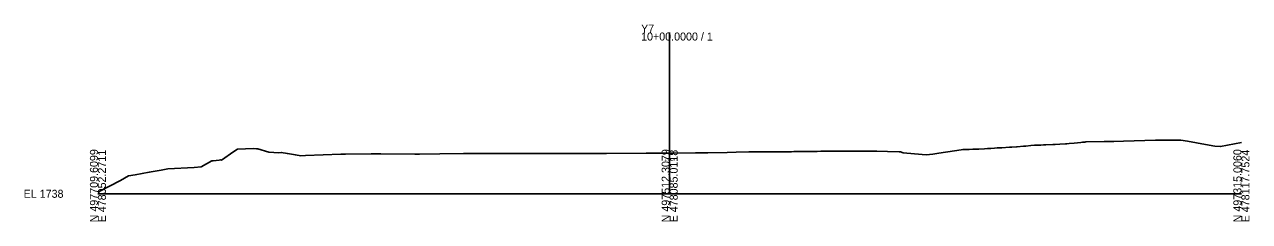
# Model space of a CAD drawing. Extents: x -26 to 403, y -10 to 4071.
# Drawn here: x -25.7 to 402.8, y -9.7 to 59.2 of the extents above; entities that cross this region are included whole.
import ezdxf

# ---------------------------------------------------------------- set-up
doc = ezdxf.new("R2010")
doc.units = 0
for name, color, linetype in [('Exist Cross Section Cell', 7, 'Continuous'), ('Exist XS Center Line Elevation Label', 7, 'Continuous'), ('Exist XS Ground Line', 7, 'Continuous'), ('Scratch_Level_5', 7, 'Continuous')]:
    doc.layers.add(name, color=color, linetype=linetype)

msp = doc.modelspace()

# ---------------------------------------------------------------- linework, layer by layer
at = {"layer": 'Exist Cross Section Cell'}
for p, q in [((200, 0), (200, 56.4)), ((0, 0), (200, 0)), ((200, 0), (400, 0))]:
    msp.add_line(p, q, dxfattribs=at)
at = {"layer": 'Exist XS Ground Line'}
msp.add_lwpolyline([(0, 0.58), (7.9, 4.61), (10.65, 6.28), (13.04, 6.64), (17.96, 7.51), (22.12, 8.29), (24.49, 8.76), (33.66, 9.18), (36.14, 9.4), (39.88, 11.54), (40.31, 11.56), (42.43, 11.79), (42.91, 11.84), (43.25, 11.77), (47.51, 14.77), (48.78, 15.56), (54.37, 15.87), (55.47, 15.76), (55.93, 15.71), (59.82, 14.59), (63.33, 14.33), (64.1, 14.46), (66.3, 14.07), (69.06, 13.6), (70.99, 13.33), (72.62, 13.36), (84.95, 13.83), (86.04, 13.87), (86.57, 13.87), (95.58, 14.03), (96.45, 14.03), (98.12, 13.96), (98.99, 13.95), (110.82, 13.83), (111.73, 13.85), (112.51, 13.85), (119.59, 13.99), (127.89, 14.04), (129.68, 14.06), (130.51, 14.07), (131.48, 14.04), (143.74, 14.12), (152.17, 14.08), (155.3, 14.1), (165.3, 14.14), (177.85, 14.14), (191.81, 14.2), (192.64, 14.2), (200, 14.24), (201.3, 14.24), (209.03, 14.34), (213.32, 14.37), (220.15, 14.44), (223.28, 14.61), (227.66, 14.65), (229.65, 14.65), (231.86, 14.66), (234.12, 14.67), (235.98, 14.66), (238.07, 14.67), (240.16, 14.7), (242.61, 14.72), (243.39, 14.73), (245.29, 14.76), (245.6, 14.76), (247.83, 14.79), (249.44, 14.81), (250.28, 14.82), (251.65, 14.83), (252.85, 14.85), (254.69, 14.87), (255.36, 14.87), (255.84, 14.87), (257.94, 14.9), (258.63, 14.9), (260.45, 14.91), (262.5, 14.91), (263.06, 14.91), (263.77, 14.91), (265.45, 14.91), (266.78, 14.91), (268.09, 14.91), (269.85, 14.92), (270.52, 14.92), (271.95, 14.91), (272.49, 14.91), (276.23, 14.82), (280.32, 14.68), (280.7, 14.67), (281.7, 14.37), (282.96, 14.17), (289.76, 13.63), (292.09, 13.9), (294.17, 14.16), (299.61, 15.03), (301.97, 15.39), (302.59, 15.49), (303.82, 15.51), (304.81, 15.54), (306, 15.56), (307.65, 15.62), (308.19, 15.64), (310.19, 15.74), (311.15, 15.8), (312.37, 15.89), (313.68, 15.97), (314.54, 16.04), (316.22, 16.11), (318.88, 16.26), (319.71, 16.32), (321.29, 16.42), (321.6, 16.44), (323.82, 16.61), (324.64, 16.67), (326.36, 16.83), (327.57, 16.95), (328.62, 16.98), (329.81, 17.04), (330.76, 17.07), (331.55, 17.1), (334.06, 17.2), (334.89, 17.25), (336.45, 17.33), (338.42, 17.48), (338.96, 17.52), (339.72, 17.58), (341.48, 17.74), (342.64, 17.85), (343.87, 17.97), (344.47, 18.02), (345.26, 18.09), (345.59, 18.12), (351.96, 18.23), (354.6, 18.27), (355.43, 18.25), (358.75, 18.41), (369.92, 18.72), (374.63, 18.8), (376.58, 18.72), (378.78, 18.8), (381.13, 18.4), (387.46, 17.27), (390.74, 16.71), (392.74, 16.51), (400, 17.96)], dxfattribs=at)
at = {"layer": 'Scratch_Level_5'}
msp.add_lwpolyline([(0, 0.58), (7.9, 4.61), (10.65, 6.28), (13.04, 6.64), (17.96, 7.51), (22.12, 8.29), (24.49, 8.76), (33.66, 9.18), (36.14, 9.4), (39.88, 11.54), (40.31, 11.56), (42.43, 11.79), (42.91, 11.84), (43.25, 11.77), (47.51, 14.77), (48.78, 15.56), (54.37, 15.87), (55.47, 15.76), (55.93, 15.71), (59.82, 14.59), (63.33, 14.33), (64.1, 14.46), (66.3, 14.07), (69.06, 13.6), (70.99, 13.33), (72.62, 13.36), (84.95, 13.83), (86.04, 13.87), (86.57, 13.87), (95.58, 14.03), (96.45, 14.03), (98.12, 13.96), (98.99, 13.95), (110.82, 13.83), (111.73, 13.85), (112.51, 13.85), (119.59, 13.99), (127.89, 14.04), (129.68, 14.06), (130.51, 14.07), (131.48, 14.04), (143.74, 14.12), (152.17, 14.08), (155.3, 14.1), (165.3, 14.14), (177.85, 14.14), (191.81, 14.2), (192.64, 14.2), (200, 14.24), (201.3, 14.24), (209.03, 14.34), (213.32, 14.37), (220.15, 14.44), (223.28, 14.61), (227.66, 14.65), (229.65, 14.65), (231.86, 14.66), (234.12, 14.67), (235.98, 14.66), (238.07, 14.67), (240.16, 14.7), (242.61, 14.72), (243.39, 14.73), (245.29, 14.76), (245.6, 14.76), (247.83, 14.79), (249.44, 14.81), (250.28, 14.82), (251.65, 14.83), (252.85, 14.85), (254.69, 14.87), (255.36, 14.87), (255.84, 14.87), (257.94, 14.9), (258.63, 14.9), (260.45, 14.91), (262.5, 14.91), (263.06, 14.91), (263.77, 14.91), (265.45, 14.91), (266.78, 14.91), (268.09, 14.91), (269.85, 14.92), (270.52, 14.92), (271.95, 14.91), (272.49, 14.91), (276.23, 14.82), (280.32, 14.68), (280.7, 14.67), (281.7, 14.37), (282.96, 14.17), (289.76, 13.63), (292.09, 13.9), (294.17, 14.16), (299.61, 15.03), (301.97, 15.39), (302.59, 15.49), (303.82, 15.51), (304.81, 15.54), (306, 15.56), (307.65, 15.62), (308.19, 15.64), (310.19, 15.74), (311.15, 15.8), (312.37, 15.89), (313.68, 15.97), (314.54, 16.04), (316.22, 16.11), (318.88, 16.26), (319.71, 16.32), (321.29, 16.42), (321.6, 16.44), (323.82, 16.61), (324.64, 16.67), (326.36, 16.83), (327.57, 16.95), (328.62, 16.98), (329.81, 17.04), (330.76, 17.07), (331.55, 17.1), (334.06, 17.2), (334.89, 17.25), (336.45, 17.33), (338.42, 17.48), (338.96, 17.52), (339.72, 17.58), (341.48, 17.74), (342.64, 17.85), (343.87, 17.97), (344.47, 18.02), (345.26, 18.09), (345.59, 18.12), (351.96, 18.23), (354.6, 18.27), (355.43, 18.25), (358.75, 18.41), (369.92, 18.72), (374.63, 18.8), (376.58, 18.72), (378.78, 18.8), (381.13, 18.4), (387.46, 17.27), (390.74, 16.71), (392.74, 16.51), (400, 17.96)], dxfattribs=at)

# ---------------------------------------------------------------- texts
at = {"layer": 'Exist Cross Section Cell'}
for s, p in [('Y7', (190, 56.4)), ('10+00.0000 / 1', (190, 53.6)), ('EL 1738', (-26, -1.4))]:
    msp.add_text(s, height=2.8, dxfattribs=at).set_placement(p)
for s, p in [('N 497709.6099', (0, -10)), ('E 478052.2711', (2.8, -10)), ('N 497512.3079', (200, -10)), ('E 478085.0118', (202.8, -10)), ('N 497315.0060', (400, -10)), ('E 478117.7524', (402.8, -10))]:
    msp.add_text(s, height=2.8, rotation=90, dxfattribs=at).set_placement(p)
at = {"layer": 'Exist XS Center Line Elevation Label'}
msp.add_text('1752.24', height=0.75, dxfattribs=at).set_placement((198.22, 11.49))

doc.saveas('drawing.dxf')
